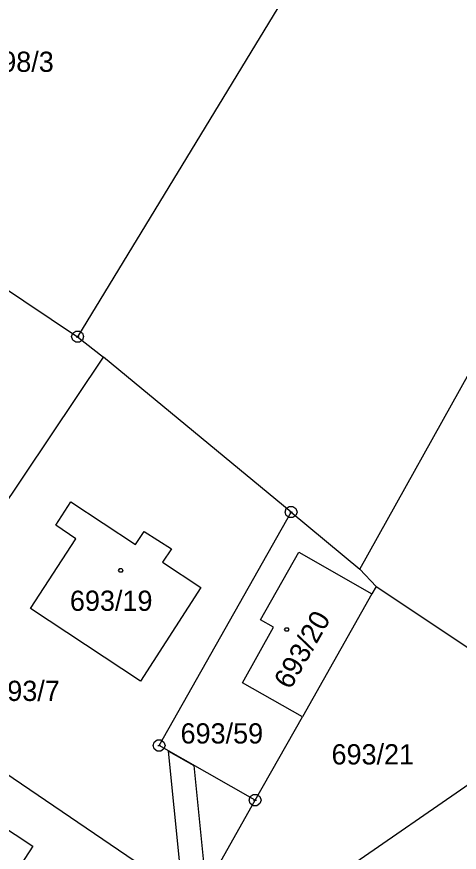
# Model space of a CAD drawing. Extents: x -759699 to -757730, y -1172308 to -1170857.
# Drawn here: x -758375.4 to -758338.2, y -1171206.6 to -1171136.3 of the extents above; entities that cross this region are included whole.
import ezdxf

# ---------------------------------------------------------------- set-up
doc = ezdxf.new("R2010")
doc.units = 0
for name, color, linetype in [('Vrstva 1', 7, 'Continuous'), ('Vrstva 12', 7, 'Continuous'), ('Vrstva 13', 7, 'Continuous'), ('Vrstva 2', 7, 'Continuous'), ('Vrstva 5', 7, 'Continuous'), ('Vrstva 8', 7, 'Continuous')]:
    doc.layers.add(name, color=color, linetype=linetype)

msp = doc.modelspace()

# ---------------------------------------------------------------- linework, layer by layer
at = {"layer": 'Vrstva 1'}
for p, q in [((-758346.54, -1171182.75), (-758307.35, -1171112.41)), ((-758353.46, -1171135.55), (-758370.31, -1171163.21)), ((-758393, -1171148.12), (-758370.31, -1171163.21)), ((-758370.31, -1171163.21), (-758368.12, -1171164.94)), ((-758386.86, -1171192.81), (-758368.12, -1171164.94)), ((-758352.33, -1171177.97), (-758368.12, -1171164.94)), ((-758372.14, -1171179.07), (-758370.87, -1171177.1)), ((-758370.87, -1171177.1), (-758365.44, -1171180.7)), ((-758363.45, -1171197.61), (-758352.33, -1171177.97)), ((-758352.33, -1171177.97), (-758346.54, -1171182.75)), ((-758370.45, -1171180.22), (-758372.14, -1171179.07)), ((-758374.29, -1171186.08), (-758370.45, -1171180.22)), ((-758365.44, -1171180.7), (-758364.7, -1171179.59)), ((-758364.7, -1171179.59), (-758362.42, -1171181.04)), ((-758362.42, -1171181.04), (-758363.16, -1171182.18)), ((-758354.92, -1171187.02), (-758351.7, -1171181.33)), ((-758351.7, -1171181.33), (-758345.53, -1171184.83)), ((-758363.16, -1171182.18), (-758359.93, -1171184.32)), ((-758345.18, -1171184.23), (-758346.54, -1171182.75)), ((-758359.93, -1171184.32), (-758365.01, -1171192.19)), ((-758345.18, -1171184.23), (-758345.53, -1171184.83)), ((-758345.18, -1171184.23), (-758332.3, -1171192.8)), ((-758345.53, -1171184.83), (-758351.39, -1171195.18)), ((-758365.01, -1171192.19), (-758374.29, -1171186.08)), ((-758353.83, -1171187.64), (-758354.92, -1171187.02)), ((-758356.44, -1171192.33), (-758353.83, -1171187.64)), ((-758386.86, -1171192.81), (-758362.75, -1171209.16)), ((-758351.39, -1171195.18), (-758356.44, -1171192.33)), ((-758365.62, -1171220.33), (-758328.98, -1171195.04)), ((-758355.37, -1171202.2), (-758351.39, -1171195.18)), ((-758355.37, -1171202.2), (-758363.45, -1171197.61)), ((-758384, -1171199.54), (-758374.07, -1171206.07)), ((-758360.06, -1171210.49), (-758355.37, -1171202.2)), ((-758374.07, -1171206.07), (-758380.71, -1171216.2))]:
    msp.add_line(p, q, dxfattribs=at)
at = {"layer": 'Vrstva 12'}
for p, q in [((-758372.14, -1171179.07), (-758370.87, -1171177.1)), ((-758370.87, -1171177.1), (-758365.44, -1171180.7)), ((-758370.45, -1171180.22), (-758372.14, -1171179.07)), ((-758374.29, -1171186.08), (-758370.45, -1171180.22)), ((-758365.44, -1171180.7), (-758364.7, -1171179.59)), ((-758364.7, -1171179.59), (-758362.42, -1171181.04)), ((-758362.42, -1171181.04), (-758363.16, -1171182.18)), ((-758354.92, -1171187.02), (-758351.7, -1171181.33)), ((-758351.7, -1171181.33), (-758345.53, -1171184.83)), ((-758363.16, -1171182.18), (-758359.93, -1171184.32)), ((-758359.93, -1171184.32), (-758365.01, -1171192.19)), ((-758345.53, -1171184.83), (-758351.39, -1171195.18)), ((-758365.01, -1171192.19), (-758374.29, -1171186.08)), ((-758353.83, -1171187.64), (-758354.92, -1171187.02)), ((-758356.44, -1171192.33), (-758353.83, -1171187.64)), ((-758351.39, -1171195.18), (-758356.44, -1171192.33)), ((-758384, -1171199.54), (-758374.07, -1171206.07)), ((-758374.07, -1171206.07), (-758380.71, -1171216.2))]:
    msp.add_line(p, q, dxfattribs=at)
at = {"layer": 'Vrstva 13'}
for p, q in [((-758361.7, -1171207.55), (-758362.65, -1171198.06)), ((-758362.65, -1171198.06), (-758360.52, -1171199.28)), ((-758360.52, -1171199.28), (-758359.65, -1171207.98))]:
    msp.add_line(p, q, dxfattribs=at)
at = {"layer": 'Vrstva 5'}
for points in [[(-758366.59, -1171182.72), (-758366.5, -1171182.87), (-758366.59, -1171183.02), (-758366.77, -1171183.02), (-758366.86, -1171182.87), (-758366.77, -1171182.72)], [(-758352.61, -1171187.69), (-758352.52, -1171187.84), (-758352.61, -1171187.99), (-758352.79, -1171187.99), (-758352.88, -1171187.84), (-758352.79, -1171187.69)]]:
    msp.add_lwpolyline(points, close=True, dxfattribs=at)
at = {"layer": 'Vrstva 8'}
for p, q in [((-758370.43, -1171163.21), (-758370.19, -1171163.21)), ((-758352.45, -1171177.97), (-758352.21, -1171177.97)), ((-758363.57, -1171197.61), (-758363.33, -1171197.61)), ((-758355.49, -1171202.2), (-758355.25, -1171202.2))]:
    msp.add_line(p, q, dxfattribs=at)
for points in [[(-758370.16, -1171162.73), (-758369.91, -1171162.91), (-758369.81, -1171163.2), (-758369.91, -1171163.49), (-758370.16, -1171163.67), (-758370.47, -1171163.67), (-758370.72, -1171163.49), (-758370.82, -1171163.2), (-758370.72, -1171162.91), (-758370.47, -1171162.73)], [(-758352.18, -1171177.49), (-758351.93, -1171177.67), (-758351.83, -1171177.96), (-758351.93, -1171178.25), (-758352.18, -1171178.43), (-758352.49, -1171178.43), (-758352.74, -1171178.25), (-758352.84, -1171177.96), (-758352.74, -1171177.67), (-758352.49, -1171177.49)], [(-758363.3, -1171197.13), (-758363.05, -1171197.31), (-758362.95, -1171197.6), (-758363.05, -1171197.89), (-758363.3, -1171198.07), (-758363.61, -1171198.07), (-758363.86, -1171197.89), (-758363.96, -1171197.6), (-758363.86, -1171197.31), (-758363.61, -1171197.13)], [(-758355.22, -1171201.72), (-758354.97, -1171201.9), (-758354.87, -1171202.19), (-758354.97, -1171202.48), (-758355.22, -1171202.66), (-758355.53, -1171202.66), (-758355.78, -1171202.48), (-758355.88, -1171202.19), (-758355.78, -1171201.9), (-758355.53, -1171201.72)]]:
    msp.add_lwpolyline(points, close=True, dxfattribs=at)

# ---------------------------------------------------------------- texts
at = {"layer": 'Vrstva 2'}
for s, p in [('698/3', (-758378.007, -1171140.93)), ('693/19', (-758370.961, -1171186.27)), ('693/7', (-758377.5, -1171193.85)), ('693/59', (-758361.646, -1171197.43)), ('693/21', (-758348.935, -1171199.19))]:
    msp.add_text(s, height=1.7, dxfattribs=at).set_placement(p)
msp.add_text('693/20', height=1.7, rotation=60.27516, dxfattribs=at).set_placement((-758352.407, -1171192.963))

doc.saveas('drawing.dxf')
